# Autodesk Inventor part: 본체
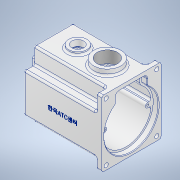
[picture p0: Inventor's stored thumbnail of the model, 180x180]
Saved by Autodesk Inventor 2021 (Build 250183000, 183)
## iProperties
Created: 2022-08
Part Number: 본체
Material: 알루미늄 6061
Document SubType Name: Modeling
Designer: Owner
Density: 2.7 g/cm^3
Appearance: 알루미늄 - 평지
Mass: 1403.34 g
Surface Area: 1174.52 cm^2
Volume: 519.757 cm^3
Author: Owner
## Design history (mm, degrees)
sketch "스케치1"
  geometry: L1 (-55, 49)-(55, 49); L2 (55, 49)-(55, -49); L3 (55, -49)-(-55, -49); L4 (-55, -49)-(-55, 49); L5 (-55, 49)-(55, -49); L6 (55, 49)-(-55, -49); 1 further point
  constraints: 12 end point, 2 midpoint, 2 parallel, 1 horizontal, 1 perpendicular
  dimensions: "d0" = 98 distance of L1.end L2.end; "d1" = 110 distance of L1.start L1.end
extrude "돌출1" new body sketch "스케치1" distance "d2" = 10; taper "d3" = 0 deg
sketch "스케치2"
  geometry: L1 (-49, 55)-(-49, -55) reference; L2 (-49, -55)-(49, -55) reference; L3 (49, -55)-(49, 55) reference; L4 (49, 55)-(-49, 55) reference; L5 (-33, -55)-(33, -55); L6 (33, -55)-(33, -38); L7 (33, 55)-(-33, 55); L8 (-33, 55)-(-33, 28); L9 (-33, -55)-(33, 55); L10 (33, -55)-(-33, 55); L11 (-49, -38)-(-33, -38); L12 (49, -38)-(49, 28); L13 (49, 28)-(33, 28); L14 (-49, 28)-(-49, -38); L15 (-49, -38)-(49, 28); L16 (49, -38)-(-49, 28); L17 (-33, 28)-(-49, 28); L18 (33, 28)-(-33, 28); L19 (-33, -38)-(-33, -55); L20 (33, -38)-(49, -38); L21 (-33, 28)-(-33, -38); L22 (33, 28)-(33, 55); L23 (33, -38)-(33, 28); L24 (-33, -38)-(33, -38); 11 further points
  constraints: 40 end point, 20 parallel, 7 midpoint, 6 perpendicular, 4 horizontal, 2 point on line
  dimensions: "d4" = 66 distance of L7.start L7.end; "d6" = 17 distance between parallel lines of L2 L11; "d7" = 27 distance between parallel lines of L4 L13
extrude "돌출2" join sketch "스케치2" distance "d8" = 120; taper "d9" = 0 deg
sketch "스케치4"
  geometry: L1 (-49, -55)-(49, -55) reference; L2 (-23, 30.143)-(-23, 45); L3 (-23, 45)-(23, 45); L4 (23, 45)-(23, 30.143); L5 (0, 0)-(0, 19.376); A1 r 42 centre (0, -5) between (-23, 30.143) and (23, 30.143)
  constraints: 8 end point, 2 perpendicular, 2 point on circle, 2 vertical, 1 centre point, 1 vertical alignment, 1 other
  dimensions: "d14" = 50 distance from line of L1 A1.centre; "d15" = 46 distance of L2.end L3.end; "d16" = 50 distance from line of A1.centre L3; "d17" = 84 diameter of A1
extrude "돌출4" cut sketch "스케치4" distance "d18" = 121; taper "d19" = 0 deg
fillet "모깎기1" dims "d20" = 6
sketch "스케치5"
  geometry: L1 (-23, 33.249)-(-23, 45) reference; L2 (-23, 45)-(23, 45) reference; L3 (23, 45)-(23, 33.249) reference; L4 (-26, 48)-(-26, 33.249); L5 (26, 33.249)-(26, 48); L6 (26, 48)-(-26, 48); A1 r 6 centre (29, 33.249) between (23, 33.249) and (25.375, 28.468) reference; A2 r 42 centre (0, -5) between (-25.375, 28.468) and (25.375, 28.468) reference; A3 r 6 centre (-29, 33.249) between (-25.375, 28.468) and (-23, 33.249) reference; A4 r 3 centre (-29, 33.249) between (-27.187, 30.859) and (-26, 33.249); A5 r 45 centre (0, -5) between (-27.187, 30.859) and (27.188, 30.859); A6 r 3 centre (29, 33.249) between (26, 33.249) and (27.188, 30.859); 1 further point
  constraints: 6 end point, 6 point on circle, 3 centre point, 5 other
  dimensions: "d21" = 3 distance between parallel lines of L1 L4
extrude "돌출5" cut sketch "스케치5" distance "d22" = 9; taper "d23" = 0 deg
sketch "스케치6"
  geometry: A1 r 42 centre (0, -5) between (-25.375, 28.468) and (25.375, 28.468) reference; A2 r 15 centre (0, -25) between (-8.978, -12.984) and (8.978, -12.984); A3 r 21 centre (0, 6) between (8.978, -12.984) and (-8.978, -12.984); 1 further point
  constraints: 4 point on circle, 2 centre point, 2 vertical alignment
  dimensions: "d24" = 30 diameter of A2; "d25" = 20 distance of A2.centre A1.centre; "d26" = 42 diameter of A3; "d27" = 11 distance of A1.centre A3.centre
extrude "돌출6" join sketch "스케치6" distance "d28" = 7; taper "d29" = 0 deg
sketch "스케치8"
  geometry: A1 r 15 centre (0, -25) between (-8.978, -12.984) and (8.978, -12.984) reference; 2 further points
  constraints: 1 coincident
hole "구멍1" sketch "스케치8" at (0, -25) diameter "d30" = 19; stored, may be unused: countersink angle "d34" = 90 deg, drill point angle "d36" = 0 deg; dims "d31" = 12, "d32" = 22, "d33" = 7, "d35" = 10
sketch "스케치10"
  geometry: A1 r 21 centre (0, 6) between (8.978, -12.984) and (-8.978, -12.984) reference; 2 further points
  constraints: 1 coincident
hole "구멍3" sketch "스케치10" at (0, 6) diameter "d44" = 35; stored, may be unused: countersink angle "d48" = 90 deg, drill point angle "d50" = 0 deg; dims "d45" = 12, "d46" = 32, "d47" = 8.3, "d49" = 10
sketch "스케치11"
  geometry: L1 (0, -5)-(36, -5); L2 (0, -5)-(-36, -5); L3 (-35.777, -1)-(-41.809, -1); L4 (-35.777, -9)-(-41.809, -9); L5 (35.777, -1)-(41.809, -1); L6 (35.777, -9)-(41.809, -9); A1 r 42 centre (0, -5) between (-25.375, 28.468) and (25.375, 28.468) reference; A2 r 45 centre (0, -5) between (-27.187, 30.859) and (27.188, 30.859) reference; A3 r 36 centre (0, -5) between (36, -5) and (-36, -5); A4 r 4 centre (36, -5) between (36, -1) and (36, -9); A5 r 4 centre (-36, -5) between (-36, -9) and (-36, -1); 1 further point
  constraints: 14 point on circle, 12 end point, 5 point on line, 4 tangent, 3 centre point, 3 coincident, 3 horizontal, 2 parallel
  dimensions: "d51" = 72 diameter of A3; "d52" = 8 diameter of A5; "d53" = 8 diameter of A4
extrude "돌출7" join sketch "스케치11" stored distance "d54" = 121; taper "d55" = 0 deg
sketch "스케치12"
  geometry: A1 r 4 centre (36, -5) between (36, -1) and (36, -9) reference; 2 further points
  constraints: 1 coincident
hole "구멍4" sketch "스케치12" at (36, -5) diameter "d56" = 3.45873; stored, may be unused: countersink angle "d60" = 90 deg, drill point angle "d62" = 118 deg; dims "d57" = 7, "d58" = 32, "d59" = 8.3, "d61" = 9
sketch "스케치13"
  geometry: A1 r 4 centre (-36, -5) between (-36, -9) and (-36, -1) reference; 2 further points
  constraints: 1 coincident
hole "구멍5" sketch "스케치13" at (-36, -5) diameter "d63" = 3.45873; stored, may be unused: countersink angle "d67" = 90 deg, drill point angle "d69" = 118 deg; dims "d64" = 7, "d65" = 32, "d66" = 8.3, "d68" = 9
sketch "스케치15"
  geometry: L1 (-27, -21)-(27, -21); L2 (27, -21)-(27, 33); L3 (27, 33)-(-27, 33); L4 (-27, 33)-(-27, -21); L5 (-27, -21)-(27, 33); L6 (27, -21)-(-27, 33); L7 (-49, -55)-(-33, -55) reference; 3 further points
  constraints: 12 end point, 3 midpoint, 2 parallel, 1 horizontal, 1 perpendicular, 1 vertical alignment
  dimensions: "d71" = 54 distance of L2.end L3.end; "d72" = 54 distance of L1.end L2.end; "d73" = 61 distance from line of L7 point (0, 6)
extrude "돌출8" join sketch "스케치15" distance "d74" = 7; taper "d75" = 0 deg
sketch "스케치16"
  geometry: A1 r 21 centre (0, 6) between (8.978, -12.984) and (-8.978, -12.984) reference; 2 further points
  constraints: 1 coincident
hole "구멍6" sketch "스케치16" at (0, 6) diameter "d76" = 28; stored, may be unused: countersink angle "d80" = 90 deg, drill point angle "d82" = 0 deg; dims "d77" = 7, "d78" = 32, "d79" = 8.3, "d81" = 52.5
fillet "모깎기2" dims "d70" = 0.3
chamfer "모따기1" distance "d83" = 0.8; stored, may be unused: second distance "d84" = 2, angle "d85" = 30 deg
sketch "스케치17"
  geometry: L1 (0, 98)-(0, 0) reference; C1 r 22.5 at (-40, 49); 2 further points
  constraints: 1 centre point, 1 horizontal alignment, 1 midpoint
  dimensions: "d86" = 45 diameter of C1; "d87" = 40 distance of point (0, 49) C1.centre
extrude "돌출9" join sketch "스케치17" distance "d88" = 10; taper "d89" = 0 deg
sketch "스케치18"
  geometry: L1 (0, 98)-(0, 0) reference; C1 r 22.5 at (-40, 49) reference; C2 r 15 at (-89, 49); 2 further points
  constraints: 1 centre point, 1 horizontal alignment, 1 midpoint
  dimensions: "d90" = 30 diameter of C2; "d91" = 49 distance of C2.centre C1.centre
extrude "돌출10" join sketch "스케치18" distance "d92" = 5; taper "d93" = 0 deg
sketch "스케치19"
  geometry: C1 r 22.5 at (0, 0) reference; 2 further points
  constraints: 1 coincident
hole "구멍7" sketch "스케치19" at (0, 0) diameter "d94" = 33.376; stored, may be unused: countersink angle "d98" = 90 deg, drill point angle "d100" = 0 deg; dims "d95" = 70, "d96" = 32, "d97" = 8.3, "d99" = 77.3
sketch "스케치21"
  geometry: C1 r 15 at (32, 23) reference; 2 further points
  constraints: 1 coincident
hole "구멍8" sketch "스케치21" at (32, 23) diameter "d101" = 20; stored, may be unused: countersink angle "d105" = 90 deg, drill point angle "d107" = 0 deg; dims "d102" = 70, "d103" = 30, "d104" = 5, "d106" = 77.3
fillet "모깎기3" dims "d108" = 3
fillet "모깎기4" dims "d109" = 3
fillet "모깎기5" dims "d110" = 3
fillet "모깎기6" dims "d111" = 3
fillet "모깎기7" dims "d112" = 3
fillet "모깎기8" dims "d113" = 3
chamfer "모따기3" distance "d118" = 1; stored, may be unused: second distance "d119" = 2, angle "d120" = 45 deg
fillet "모깎기10" dims "d121" = 3
sketch "스케치22"
  geometry: L1 (46, 55)-(-46, 55) reference; L2 (-49, 52)-(-49, -52) reference; 2 further points
  dimensions: "d129" = 7 distance from line of L1 point (-42, 48); "d130" = 7 distance from line of L2 point (-42, 48)
hole "구멍9" sketch "스케치22" at (-42, 48) diameter "d122" = 7; stored, may be unused: countersink angle "d126" = 90 deg, drill point angle "d128" = 0 deg; dims "d123" = 70, "d124" = 32, "d125" = 8.3, "d127" = 77.3
fillet "모깎기11" dims "d137" = 3
fillet "모깎기12" dims "d138" = 3
sketch "스케치23"
  geometry: L1 (-130, 104)-(-130, 83) reference; L2 (-13, 80)-(-127, 80) reference; 2 further points
  constraints: 1 other
  dimensions: "d139" = 65 distance from line of L1 point (-65, 47); "d140" = 33 distance from line of L2 point (-65, 47)
feature "엠보싱1" sketch "스케치23" dims "d141" = 0.5, "d142" = 0
fillet "모깎기13" dims "d143" = 6
fillet "모깎기14" dims "d144" = 3
chamfer "모따기4" distance "d145" = 1; stored, may be unused: second distance "d146" = 2, angle "d147" = 45 deg
fillet "모깎기15" dims "d148" = 3
fillet "모깎기16" dims "d149" = 3
node "솔리드1"
pattern_linear "직사각형 패턴1" dims "d133" = 84, "d136" = 96
feature "A9D066F2-1C7D-4E18-AEED-F7BC21143FA4" dims "d30" = 19, "d31" = 12, "d32" = 22, "d33" = 7, "d34" = 90 deg, "d35" = 10, "d36" = 0
